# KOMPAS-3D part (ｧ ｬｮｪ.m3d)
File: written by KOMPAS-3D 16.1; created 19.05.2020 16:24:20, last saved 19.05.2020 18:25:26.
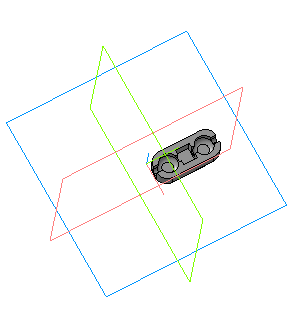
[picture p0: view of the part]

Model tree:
1. Эскиз:1
2. Операция выдавливания:1
     Расстояние 1 = 5.4
3. Эскиз:3
4. Вырезать элемент выдавливания:2
     Расстояние 1 = 4; Угол 1 = 5
5. Эскиз:4
6. Вырезать элемент выдавливания:3
     Расстояние 1 = 4
7. Эскиз:2
8. Вырезать элемент выдавливания:1
     Расстояние 1 = 3
9. Скругление:1
     Радиус = 3
10. Скругление:2
     Радиус = 1.2
11. Скругление:3
     Радиус = 1.2
12. Скругление:4
     Радиус = 1
13. Зеркальный массив:1
14. Экземпляр ( 1 )
15. Экземпляр ( 2 )  (with: Операция выдавливания:1, Вырезать элемент выдавливания:2, Вырезать элемент выдавливания:3, Вырезать элемент выдавливания:1, Скругление:1, Скругление:2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)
